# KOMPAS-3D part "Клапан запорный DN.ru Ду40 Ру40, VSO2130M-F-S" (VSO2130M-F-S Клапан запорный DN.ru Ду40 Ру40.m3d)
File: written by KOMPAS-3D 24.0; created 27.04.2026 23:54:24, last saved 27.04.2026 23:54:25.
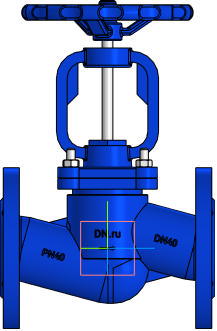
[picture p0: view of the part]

Document properties: Автор: DN.ru; Полное имя файла: C:\Работа\ГОТОВЫЕ ИСХОДНИКИ\VSO2130M-F-S Клапан запорный сальниковый DN.ru Ду15-100 Ру40\DN40\VSO2130M-F-S Клапан запорный DN.ru Ду40 Ру40.m3d

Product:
- Part/product: Клапан запорный DN.ru Ду40 Ру40  | designation VSO2130M-F-S
    Масса: 13.5
    Раздел спецификации: Прочие изделия
    Примечание: D090-01983

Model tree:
1. Операция без истории:1

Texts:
  VSO2130M-F-S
